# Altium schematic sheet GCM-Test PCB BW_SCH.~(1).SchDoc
size C
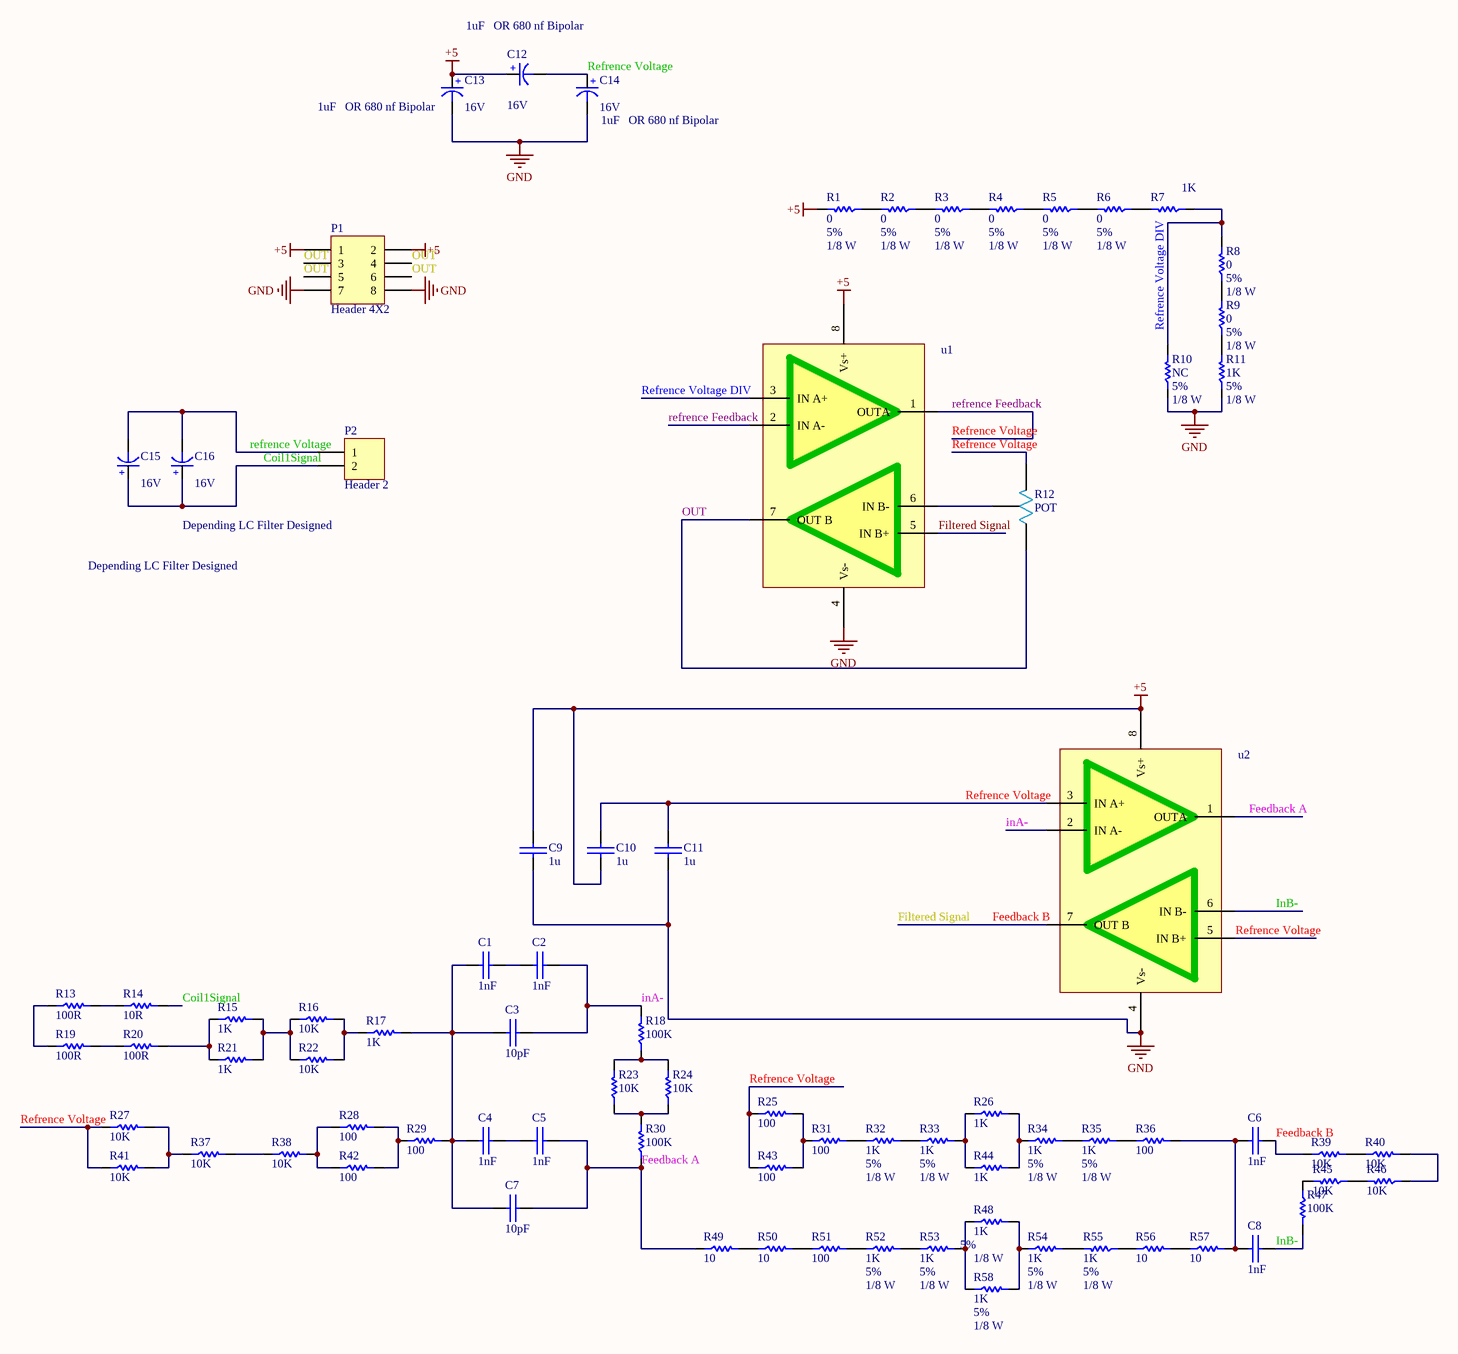
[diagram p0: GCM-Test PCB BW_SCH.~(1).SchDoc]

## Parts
C1  1nF  [SMD_CAP_1206]
C2  1nF  [SMD_CAP_1206]
C3  10pF  [SMD_CAP_1206]
C4  1nF  [SMD_CAP_1206]
C5  1nF  [SMD_CAP_1206]
C6  1nF  [SMD_CAP_1206]
C7  10pF  [SMD_CAP_1206]
C8  1nF  [SMD_CAP_1206]
C9  1u  [SMD_CAP_1206]
C10  1u  [SMD_CAP_1206]
C11  1u  [SMD_CAP_1206]
C12  Voltage: 16V  [cap 01]  (hidden comment: 1uF   OR 680 nf Bipolar)
C13  Voltage: 16V  [cap 01]  (hidden comment: 1uF   OR 680 nf Bipolar)
C14  Voltage: 16V  [cap 01]  (hidden comment: 1uF   OR 680 nf Bipolar)
C15  Voltage: 16V  [cap 01]  (hidden comment: Depending LC Filter Designed)
C16  Voltage: 16V  [cap 01]  (hidden comment: Depending LC Filter Designed)
P1  Header 4X2  [HDR2X4]
P2  Header 2  [HDR1X2]
R1  Tolerance: 5%  Power: 1/8 W  [RES 1206 (3216X08L)]  (hidden comment: 0)
R2  Tolerance: 5%  Power: 1/8 W  [RES 1206 (3216X08L)]  (hidden comment: 0)
R3  Tolerance: 5%  Power: 1/8 W  [RES 1206 (3216X08L)]  (hidden comment: 0)
R4  Tolerance: 5%  Power: 1/8 W  [RES 1206 (3216X08L)]  (hidden comment: 0)
R5  Tolerance: 5%  Power: 1/8 W  [RES 1206 (3216X08L)]  (hidden comment: 0)
R6  Tolerance: 5%  Power: 1/8 W  [RES 1206 (3216X08L)]  (hidden comment: 0)
R7  1K  [RES 1206 (3216X08L)]
R8  Tolerance: 5%  Power: 1/8 W  [RES 1206 (3216X08L)]  (hidden comment: 0)
R9  Tolerance: 5%  Power: 1/8 W  [RES 1206 (3216X08L)]  (hidden comment: 0)
R10  Tolerance: 5%  Power: 1/8 W  [RES 1206 (3216X08L)]  (hidden comment: NC)
R11  Tolerance: 5%  Power: 1/8 W  [RES 1206 (3216X08L)]  (hidden comment: 1K)
R12  POT  [MOL_1]
R13  100R  [RES 1206 (3216X08L)]
R14  10R  [RES 1206 (3216X08L)]
R15  1K  [RES 1206 (3216X08L)]
R16  10K  [RES 1206 (3216X08L)]
R17  1K  [RES 1206 (3216X08L)]
R18  100K  [RES 1206 (3216X08L)]
R19  100R  [RES 1206 (3216X08L)]
R20  100R  [RES 1206 (3216X08L)]
R21  1K  [RES 1206 (3216X08L)]
R22  10K  [RES 1206 (3216X08L)]
R23  10K  [RES 1206 (3216X08L)]
R24  10K  [RES 1206 (3216X08L)]
R25  100  [RES 1206 (3216X08L)]
R26  1K  [RES 1206 (3216X08L)]
R27  10K  [RES 1206 (3216X08L)]
R28  100  [RES 1206 (3216X08L)]
R29  100  [RES 1206 (3216X08L)]
R30  100K  [RES 1206 (3216X08L)]
R31  100  [RES 1206 (3216X08L)]
R32  Tolerance: 5%  Power: 1/8 W  [RES 1206 (3216X08L)]  (hidden comment: 1K)
R33  Tolerance: 5%  Power: 1/8 W  [RES 1206 (3216X08L)]  (hidden comment: 1K)
R34  Tolerance: 5%  Power: 1/8 W  [RES 1206 (3216X08L)]  (hidden comment: 1K)
R35  Tolerance: 5%  Power: 1/8 W  [RES 1206 (3216X08L)]  (hidden comment: 1K)
R36  100  [RES 1206 (3216X08L)]
R37  10K  [RES 1206 (3216X08L)]
R38  10K  [RES 1206 (3216X08L)]
R39  10K  [RES 1206 (3216X08L)]
R40  10K  [RES 1206 (3216X08L)]
R41  10K  [RES 1206 (3216X08L)]
R42  100  [RES 1206 (3216X08L)]
R43  100  [RES 1206 (3216X08L)]
R44  1K  [RES 1206 (3216X08L)]
R45  10K  [RES 1206 (3216X08L)]
R46  10K  [RES 1206 (3216X08L)]
R47  100K  [RES 1206 (3216X08L)]
R48  Tolerance: 5%  Power: 1/8 W  [RES 0805 (2012X06L)]  (hidden comment: 1K)
R49  10  [RES 0805 (2012X06L)]
R50  10  [RES 0805 (2012X06L)]
R51  100  [RES 0805 (2012X06L)]
R52  Tolerance: 5%  Power: 1/8 W  [RES 1206 (3216X08L)]  (hidden comment: 1K)
R53  Tolerance: 5%  Power: 1/8 W  [RES 1206 (3216X08L)]  (hidden comment: 1K)
R54  Tolerance: 5%  Power: 1/8 W  [RES 1206 (3216X08L)]  (hidden comment: 1K)
R55  Tolerance: 5%  Power: 1/8 W  [RES 1206 (3216X08L)]  (hidden comment: 1K)
R56  10  [RES 0805 (2012X06L)]
R57  10  [RES 0805 (2012X06L)]
R58  Tolerance: 5%  Power: 1/8 W  [RES 0805 (2012X06L)]  (hidden comment: 1K)
u1  LM358N  [lm358 dip]  (value not drawn)
u2  LM358N  [lm358 dip]  (value not drawn)

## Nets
+5: C9.1(+) C10.2(-) C12.1(+) C13.1(+) P1.1 P1.2 R1.2 u1.8(Vs+) u2.8(Vs+)
GND: C9.2(-) C11.2(-) C13.2(-) C14.2(-) P1.7 P1.8 R10.1 R11.1 u1.4(Vs-) u2.4(Vs-)
Coil1Signal: C15.1(+) C16.1(+) P2.2 R14.2
Feedback A: C5.2(-) C7.2(-) R30.1 R49.1 u2.1(OUTA)
Feedback B: C6.2(-) R39.1 u1.5(IN_B+) u2.7(OUT_B)  [also labelled Filtered Signal]
inA-: C2.2(-) C3.2(-) R18.2 u2.2(IN_A-)
InB-: C8.2(-) R47.2 u2.6(IN_B-)
OUT: P1.3 P1.4 P1.5 P1.6 R12.1 u1.7(OUT_B)
refrence Feedback: C10.1(+) C11.1(+) C12.2(-) C14.1(+) C15.2(-) C16.2(-) P2.1 R12.3 R25.1 R27.1 R41.1 R43.1 u1.1(OUTA) u1.2(IN_A-) u2.3(IN_A+) u2.5(IN_B+)  [also labelled Refrence Voltage]
Refrence Voltage DIV: R7.1 R8.2 R10.2 u1.3(IN_A+)
NetC1_1: C1.1(+) C3.1(+) C4.1(+) C7.1(+) R17.2 R29.2
NetC1_2: C1.2(-) C2.1(+)
NetC4_2: C4.2(-) C5.1(+)
NetC6_1: C6.1(+) C8.1(+) R36.2 R57.2
NetR1_1: R1.1 R2.2
NetR2_1: R2.1 R3.2
NetR3_1: R3.1 R4.2
NetR4_1: R4.1 R5.2
NetR5_1: R5.1 R6.2
NetR6_1: R6.1 R7.2
NetR8_1: R8.1 R9.2
NetR9_1: R9.1 R11.2
NetR12_2: R12.2 u1.6(IN_B-)
NetR13_1: R13.1 R19.1
NetR13_2: R13.2 R14.1
NetR15_1: R15.1 R20.2 R21.1
NetR15_2: R15.2 R16.1 R21.2 R22.1
NetR16_2: R16.2 R17.1 R22.2
NetR18_1: R18.1 R23.2 R24.2
NetR19_2: R19.2 R20.1
NetR23_1: R23.1 R24.1 R30.2
NetR25_2: R25.2 R31.1 R43.2
NetR26_1: R26.1 R33.2 R44.1
NetR26_2: R26.2 R34.1 R44.2
NetR27_2: R27.2 R37.1 R41.2
NetR28_1: R28.1 R38.2 R42.1
NetR28_2: R28.2 R29.1 R42.2
NetR31_2: R31.2 R32.1
NetR32_2: R32.2 R33.1
NetR34_2: R34.2 R35.1
NetR35_2: R35.2 R36.1
NetR37_2: R37.2 R38.1
NetR39_2: R39.2 R40.1
NetR40_2: R40.2 R46.1
NetR45_1: R45.1 R46.2
NetR45_2: R45.2 R47.1
NetR48_1: R48.1 R53.2 R58.1
NetR48_2: R48.2 R54.1 R58.2
NetR49_2: R49.2 R50.1
NetR50_2: R50.2 R51.1
NetR51_2: R51.2 R52.1
NetR52_2: R52.2 R53.1
NetR54_2: R54.2 R55.2
NetR55_1: R55.1 R56.1
NetR56_2: R56.2 R57.1

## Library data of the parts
C1-C11 = Cap-Bipolar: Bipolar Capacitor; Voltage: 100V; Designer: Saeid Jorablo; Organazation: ControTec
C12-C16 = Cap-Polar: Polar Capacitor; Designer: Saeid Jorablo; Organazation: ControTec
P1 = Header 4X2: Header, 4-Pin, Dual row
P2 = Header 2: Header, 2-Pin
R1-R6 R8-R11 R32-R35 R48 R52-R55 R58 = Resistor
R7 R13-R31 R36-R47 R49-R51 R56 R57 = Resistor: Tolerance: 5%; Power: 1/8 W
u1 u2 = LM358N: DESIGNER: Ehsan Shaghaei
